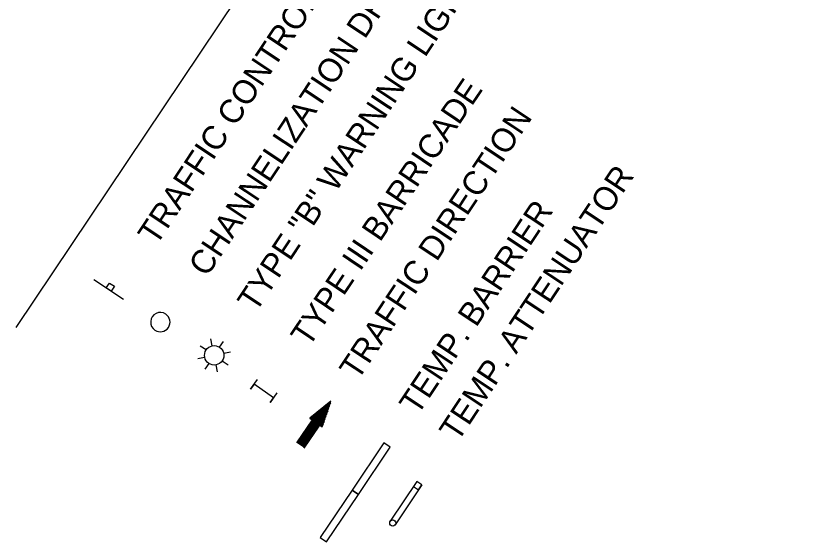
# Model space of a CAD drawing. Extents: x 1795987 to 1799689, y 243690 to 251545.
# Drawn here: x 1798551.7 to 1798817.1, y 250324.5 to 250497.4 of the extents above; entities that cross this region are included whole.
import ezdxf

# ---------------------------------------------------------------- set-up
doc = ezdxf.new("R2010")
doc.units = 0
doc.layers.add('LEGEND', color=7, linetype='Continuous')
doc.layers.add('Level 2', color=7, linetype='Continuous')

# ---------------------------------------------------------------- blocks, each defined once
blk = doc.blocks.new('T21LR')
at = {"layer": 'Level 2'}
for p, q in [((0, 2), (31.5, 2)), ((0, -2), (31.5, -2))]:
    blk.add_line(p, q, dxfattribs=at)
blk.add_lwpolyline([(0, -2), (4, -2), (4, 2), (0, 2)], close=True, dxfattribs=at)
blk.add_circle((31.5, 0), 2, dxfattribs=at)

msp = doc.modelspace()

# ---------------------------------------------------------------- linework, layer by layer
at = {"layer": 'LEGEND'}
for p, q in [((1798551.69, 250395.05), (1798817.07, 250790.3)), ((1798587.01, 250404.22), (1798577.3, 250410.74)), ((1798616.22, 250389), (1798615.77, 250391.27)), ((1798614.18, 250387.64), (1798612.27, 250388.93)), ((1798618.62, 250388.52), (1798619.9, 250390.43)), ((1798622.24, 250386.93), (1798619.97, 250386.48)), ((1798611.43, 250384.8), (1798613.7, 250385.25)), ((1798615.06, 250383.21), (1798613.77, 250381.29)), ((1798619.49, 250384.08), (1798621.41, 250382.79)), ((1798617.9, 250380.46), (1798617.45, 250382.73)), ((1798655.26, 250370.85), (1798648.28, 250365.16)), ((1798652.4, 250362.31), (1798655.26, 250370.85)), ((1798649.05, 250364.62), (1798643.89, 250357.15)), ((1798648.28, 250365.16), (1798649.05, 250364.62)), ((1798646.46, 250355.37), (1798651.62, 250362.85)), ((1798651.62, 250362.85), (1798652.4, 250362.31))]:
    msp.add_line(p, q, dxfattribs=at)
for points in [[(1798581.34, 250408.03), (1798582.43, 250409.65), (1798584.05, 250408.56), (1798582.96, 250406.94)], [(1798674.7, 250355.67), (1798672.63, 250357.06), (1798662.18, 250341.49), (1798664.26, 250340.1)], [(1798664.26, 250340.1), (1798662.18, 250341.49), (1798651.73, 250325.93), (1798653.81, 250324.53)]]:
    msp.add_lwpolyline(points, close=True, dxfattribs=at)
for points in [[(1798637.47, 250373.52), (1798635.24, 250370.32), (1798636.36, 250371.92), (1798629.95, 250376.37), (1798628.84, 250374.77), (1798631.07, 250377.97)], [(1798654.26, 250370.04), (1798644.88, 250356.46)], [(1798654.98, 250370.63), (1798645.1, 250356.32)], [(1798655.07, 250370.3), (1798645.31, 250356.17)], [(1798651.36, 250367.67), (1798644.03, 250357.05)], [(1798652.09, 250368.26), (1798644.24, 250356.91)], [(1798652.81, 250368.86), (1798644.46, 250356.76)], [(1798653.54, 250369.45), (1798644.67, 250356.61)], [(1798654.77, 250369.41), (1798645.52, 250356.02)], [(1798654.48, 250368.52), (1798645.74, 250355.87)], [(1798654.18, 250367.64), (1798645.95, 250355.73)], [(1798653.88, 250366.75), (1798646.17, 250355.58)], [(1798653.59, 250365.86), (1798646.38, 250355.43)], [(1798648.46, 250365.31), (1798648.33, 250365.12)], [(1798649.19, 250365.9), (1798648.55, 250364.97)], [(1798649.91, 250366.49), (1798648.76, 250364.82)], [(1798650.64, 250367.08), (1798648.98, 250364.68)], [(1798653.29, 250364.97), (1798651.76, 250362.75)], [(1798652.99, 250364.09), (1798651.97, 250362.61)], [(1798652.69, 250363.2), (1798652.18, 250362.46)]]:
    msp.add_lwpolyline(points, dxfattribs=at)
msp.add_circle((1798616.84, 250385.86), 3.19, dxfattribs=at)
for start, end in [(56.1222, 236.1222), (236.1222, 56.1222)]:
    msp.add_arc((1798599.13, 250396.78), 3.18, start, end, dxfattribs=at)

# ---------------------------------------------------------------- block references
at = {"layer": 'LEGEND', "xscale": 0.5000000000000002, "yscale": 0.5000000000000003, "rotation": -123.72854882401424}
msp.add_blockref('T21LR', (1798684.34, 250343.84), dxfattribs=at)

# ---------------------------------------------------------------- texts
at = {"layer": 'LEGEND'}
for s, rotation, p in [('TRAFFIC CONTROL SIGN', 56.4352, (1798597.78, 250421.64)), ('CHANNELIZATION DRUM', 56.4352, (1798614.45, 250411.34)), ('TYPE "B" WARNING LIGHT', 56.4352, (1798630.52, 250399.65)), ('TYPE III BARRICADE', 55.9561, (1798648, 250388.28)), ('TRAFFIC DIRECTION', 56.4352, (1798664.08, 250377.29)), ('TEMP. ATTENUATOR', 56.4352, (1798696.96, 250357.06)), ('TEMP. BARRIER', 56.4352, (1798683.78, 250365.84))]:
    msp.add_text(s, height=7.7999, rotation=rotation, dxfattribs=at).set_placement(p)

doc.saveas('drawing.dxf')
